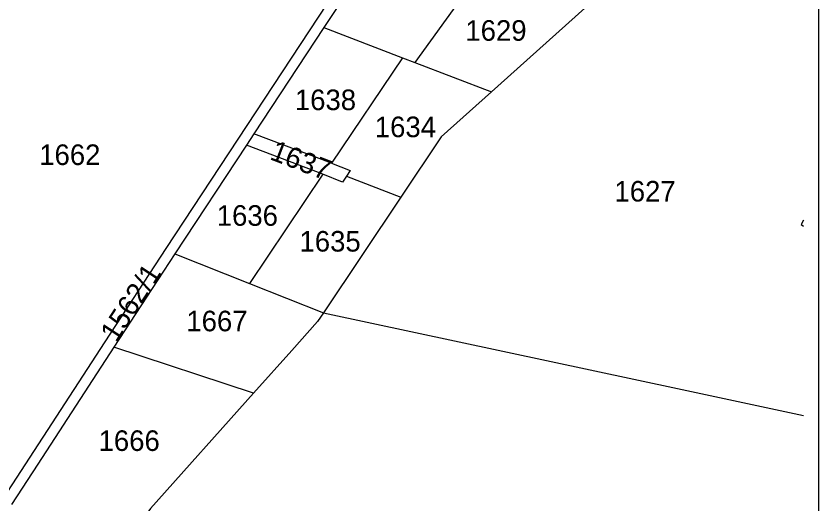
# Model space of a CAD drawing. Extents: x -583889 to -582839, y -1166553 to -1165065.
# Drawn here: x -583111.8 to -582838.7, y -1165500.8 to -1165334.9 of the extents above; entities that cross this region are included whole.
import ezdxf

# ---------------------------------------------------------------- set-up
doc = ezdxf.new("R2010")
doc.units = 0
for name, color, linetype in [('56', 7, 'Continuous'), ('Popis cest', 7, 'Continuous'), ('Vrstva 2', 7, 'Continuous')]:
    doc.layers.add(name, color=color, linetype=linetype)

msp = doc.modelspace()

# ---------------------------------------------------------------- linework, layer by layer
at = {"layer": '56'}
msp.add_lwpolyline([(-583888.67, -1166552.78), (-582838.67, -1166552.78), (-582838.67, -1165067.78), (-583888.67, -1165067.78), (-583888.67, -1166552.78)], dxfattribs=at)
at = {"layer": 'Vrstva 2'}
for p, q in [((-582987.21, -1165308.59), (-583007.11, -1165338.81)), ((-582954.72, -1165321.03), (-582976.18, -1165350.65)), ((-582918.34, -1165332.17), (-582950.06, -1165360.65)), ((-583007.11, -1165338.81), (-583030.89, -1165374.9)), ((-583007.11, -1165338.81), (-582980.36, -1165349.05)), ((-582980.36, -1165349.05), (-583004.55, -1165384.98)), ((-582980.36, -1165349.05), (-582976.18, -1165350.65)), ((-582976.18, -1165350.65), (-582950.06, -1165360.65)), ((-583030.89, -1165374.9), (-583033.44, -1165378.77)), ((-583004.55, -1165384.98), (-583030.89, -1165374.9)), ((-583033.44, -1165378.77), (-583057.85, -1165415.82)), ((-583007.52, -1165388.67), (-583033.44, -1165378.77)), ((-583007.52, -1165388.67), (-583032.38, -1165425.88)), ((-582999.45, -1165389.32), (-582980.91, -1165396.48)), ((-582980.91, -1165396.48), (-583007.29, -1165435.79)), ((-583057.85, -1165415.82), (-583032.38, -1165425.88)), ((-583032.38, -1165425.88), (-583007.29, -1165435.79)), ((-583031.01, -1165463.11), (-583078.55, -1165447.56))]:
    msp.add_line(p, q, dxfattribs=at)
for points in [[(-583150.03, -1165547.02), (-583146.45, -1165545.26), (-583081.48, -1165445.65), (-583060.78, -1165413.9), (-582999.79, -1165321.21), (-583000.42, -1165318.79)], [(-582950.06, -1165360.65), (-582967.17, -1165376.01), (-582980.91, -1165396.48)], [(-583004.55, -1165384.98), (-582998.17, -1165387.42), (-582999.45, -1165389.32)], [(-582999.45, -1165389.32), (-583000.82, -1165391.34), (-583007.52, -1165388.67)], [(-582843.89, -1165404.37), (-582844.73, -1165405.8), (-582843.89, -1165406.35)], [(-583057.85, -1165415.82), (-583067.46, -1165430.56), (-583078.55, -1165447.56)], [(-583007.29, -1165435.79), (-583009.3, -1165438.8), (-583018.06, -1165448.61), (-583031.01, -1165463.11)], [(-583007.29, -1165435.79), (-582885.16, -1165461.96), (-582843.89, -1165470.8)], [(-583078.55, -1165447.56), (-583104.44, -1165487.27), (-583113.44, -1165501.07)], [(-583031.01, -1165463.11), (-583066.05, -1165502.38), (-583075.83, -1165515.92)]]:
    msp.add_lwpolyline(points, dxfattribs=at)

# ---------------------------------------------------------------- texts
at = {"layer": 'Popis cest'}
for s, p in [('1629', (-582958.97, -1165343.3)), ('1638', (-583016.98, -1165366.89)), ('1634', (-582989.79, -1165376.09)), ('1662', (-583103.96, -1165385.56)), ('1627', (-582908.24, -1165397.98)), ('1636', (-583043.56, -1165406.23)), ('1635', (-583015.41, -1165415)), ('1667', (-583053.9, -1165442.11)), ('1666', (-583083.77, -1165482.81))]:
    msp.add_text(s, height=7, dxfattribs=at).set_placement(p)
for s, rotation, p in [('1637', 339, (-583025.86, -1165383.5)), ('1562/1', 57, (-583077.76, -1165446.22))]:
    msp.add_text(s, height=7, rotation=rotation, dxfattribs=at).set_placement(p)

doc.saveas('drawing.dxf')
